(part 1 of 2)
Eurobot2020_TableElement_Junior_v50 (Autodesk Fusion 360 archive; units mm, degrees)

design "TableElement2020" references "Balise Rouge", "Table2020", "Balise Verte"
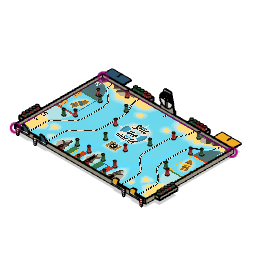
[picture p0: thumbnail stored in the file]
component_insert "Component Insert1"
component_insert "Component Insert21"
component_insert "Component Insert22"
component_insert "Component Insert23"
component_insert "Component Insert24"
component_insert "Component Insert25"
component_insert "Component Insert26"
component_insert "Component Insert27"
component_insert "Component Insert28"
component_insert "Component Insert29"
component_insert "Component Insert30"
component_insert "Component Insert31"
component_insert "Component Insert32"
component_insert "Component Insert33"
component_insert "Component Insert34"
component_insert "Component Insert35"
component_insert "Component Insert36"
component_insert "Component Insert37"
component_insert "Component Insert38"
component_insert "Component Insert39"
component_insert "Component Insert40"
component_insert "Component Insert41"
component_insert "Component Insert42"
component_insert "Component Insert43"
component_insert "Component Insert44"
component_insert "Component Insert45"
component_insert "Component Insert46"
component_insert "Component Insert47"
component_insert "Component Insert48"
component_insert "Component Insert49"
component_insert "Component Insert50"
component_insert "Component Insert51"
component_insert "Component Insert52"
component_insert "Component Insert53"
component_insert "Component Insert54"
component_insert "Component Insert55"
component_insert "Component Insert56"
position "Position1"
joint "Assemble1" OffsetX 0 OffsetY 0 OffsetZ 0 AngleZ 0 OffsetX 0 OffsetY 0 OffsetZ 0 AngleZ 0 alignAngle 0 alignOffsetX 300 alignOffsetY -400 alignOffsetZ 0 OffsetX 0 OffsetY 0 OffsetZ 0 AngleZ 0 OffsetX 0 OffsetY 0 OffsetZ 0 AngleZ 0 OffsetX 0 OffsetY 0 OffsetZ 0 AngleZ 0 OffsetX 0 OffsetY 0 OffsetZ 0 AngleZ 0 OffsetX 0 OffsetY 0 OffsetZ 0 AngleZ 0 OffsetX 0 OffsetY 0 OffsetZ 0 AngleZ 0 OffsetX 0 OffsetY 0 OffsetZ 0 AngleZ 0 OffsetX 0 OffsetY 0 OffsetZ 0 AngleZ 0 OffsetX 0 OffsetY 0 OffsetZ 0 AngleZ 0 OffsetX 0 OffsetY 0 OffsetZ 0 AngleZ 0
joint "Assemble2" OffsetX 0 OffsetY 0 OffsetZ 0 AngleZ 0 OffsetX 0 OffsetY 0 OffsetZ 0 AngleZ 0 alignAngle 0 alignOffsetX 450 alignOffsetY -509 alignOffsetZ 0 OffsetX 0 OffsetY 0 OffsetZ 0 AngleZ 0 OffsetX 0 OffsetY 0 OffsetZ 0 AngleZ 0 OffsetX 0 OffsetY 0 OffsetZ 0 AngleZ 0 OffsetX 0 OffsetY 0 OffsetZ 0 AngleZ 0
joint "Assemble3" OffsetX 0 OffsetY 0 OffsetZ 0 AngleZ 0 OffsetX 0 OffsetY 0 OffsetZ 0 AngleZ 0 alignAngle 0 alignOffsetX 450 alignOffsetY -1080 alignOffsetZ 0 OffsetX 0 OffsetY 0 OffsetZ 0 AngleZ 0 OffsetX 0 OffsetY 0 OffsetZ 0 AngleZ 0
joint "Assemble4" OffsetX 0 OffsetY 0 OffsetZ 0 AngleZ 0 OffsetX 0 OffsetY 0 OffsetZ 0 AngleZ 0 alignAngle 0 alignOffsetX 300 alignOffsetY -1200 alignOffsetZ 0 OffsetX 0 OffsetY 0 OffsetZ 0 AngleZ 0 OffsetX 0 OffsetY 0 OffsetZ 0 AngleZ 0
joint "Assemble5" OffsetX 0 OffsetY 0 OffsetZ 0 AngleZ 0 OffsetX 0 OffsetY 0 OffsetZ 0 AngleZ 0 alignAngle 0 alignOffsetX 670 alignOffsetY -100 alignOffsetZ 0 OffsetX 0 OffsetY 0 OffsetZ 0 AngleZ 0 OffsetX 0 OffsetY 0 OffsetZ 0 AngleZ 0 OffsetX 0 OffsetY 0 OffsetZ 0 AngleZ 0 OffsetX 0 OffsetY 0 OffsetZ 0 AngleZ 0 OffsetX 0 OffsetY 0 OffsetZ 0 AngleZ 0 OffsetX 0 OffsetY 0 OffsetZ 0 AngleZ 0
joint "Assemble6" OffsetX 0 OffsetY 0 OffsetZ 0 AngleZ 0 OffsetX 0 OffsetY 0 OffsetZ 0 AngleZ 0 alignAngle 0 alignOffsetX 950 alignOffsetY -400 alignOffsetZ 0 OffsetX 0 OffsetY 0 OffsetZ 0 AngleZ 0 OffsetX 0 OffsetY 0 OffsetZ 0 AngleZ 0 OffsetX 0 OffsetY 0 OffsetZ 0 AngleZ 0 OffsetX 0 OffsetY 0 OffsetZ 0 AngleZ 0
joint "Assemble7" OffsetX 0 OffsetY 0 OffsetZ 0 AngleZ 0 OffsetX 0 OffsetY 0 OffsetZ 0 AngleZ 0 alignAngle 0 alignOffsetX 1100 alignOffsetY -800 alignOffsetZ 0 OffsetX 0 OffsetY 0 OffsetZ 0 AngleZ 0 OffsetX 0 OffsetY 0 OffsetZ 0 AngleZ 0 OffsetX 0 OffsetY 0 OffsetZ 0 AngleZ 0 OffsetX 0 OffsetY 0 OffsetZ 0 AngleZ 0
joint "Assemble8" OffsetX 0 OffsetY 0 OffsetZ 0 AngleZ 0 OffsetX 0 OffsetY 0 OffsetZ 0 AngleZ 0 alignAngle 0 alignOffsetX 1270 alignOffsetY -1200 alignOffsetZ 0 OffsetX 0 OffsetY 0 OffsetZ 0 AngleZ 0 OffsetX 0 OffsetY 0 OffsetZ 0 AngleZ 0 OffsetX 0 OffsetY 0 OffsetZ 0 AngleZ 0 OffsetX 0 OffsetY 0 OffsetZ 0 AngleZ 0
joint "Assemble9" OffsetX 0 OffsetY 0 OffsetZ 0 AngleZ 0 OffsetX 0 OffsetY 0 OffsetZ 0 AngleZ 0 alignAngle 0 alignOffsetX 1730 alignOffsetY -1200 alignOffsetZ 0 OffsetX 0 OffsetY 0 OffsetZ 0 AngleZ 0 OffsetX 0 OffsetY 0 OffsetZ 0 AngleZ 0
joint "Assemble10" OffsetX 0 OffsetY 0 OffsetZ 0 AngleZ 0 OffsetX 0 OffsetY 0 OffsetZ 0 AngleZ 0 alignAngle 0 alignOffsetX 1900 alignOffsetY -800 alignOffsetZ 0 OffsetX 0 OffsetY 0 OffsetZ 0 AngleZ 0 OffsetX 0 OffsetY 0 OffsetZ 0 AngleZ 0
joint "Assemble11" OffsetX 0 OffsetY 0 OffsetZ 0 AngleZ 0 OffsetX 0 OffsetY 0 OffsetZ 0 AngleZ 0 alignAngle 0 alignOffsetX 2050 alignOffsetY -400 alignOffsetZ 0 OffsetX 0 OffsetY 0 OffsetZ 0 AngleZ 0 OffsetX 0 OffsetY 0 OffsetZ 0 AngleZ 0 OffsetX 0 OffsetY 0 OffsetZ 0 AngleZ 0 OffsetX 0 OffsetY 0 OffsetZ 0 AngleZ 0
joint "Assemble12" OffsetX 0 OffsetY 0 OffsetZ 0 AngleZ 0 OffsetX 0 OffsetY 0 OffsetZ 0 AngleZ 0 alignAngle 0 alignOffsetX 2330 alignOffsetY -100 alignOffsetZ 0 OffsetX 0 OffsetY 0 OffsetZ 0 AngleZ 0 OffsetX 0 OffsetY 0 OffsetZ 0 AngleZ 0
joint "Assemble13" OffsetX 0 OffsetY 0 OffsetZ 0 AngleZ 0 OffsetX 0 OffsetY 0 OffsetZ 0 AngleZ 0 alignAngle 0 alignOffsetX 2700 alignOffsetY -400 alignOffsetZ 0
joint "Assemble14" OffsetX 0 OffsetY 0 OffsetZ 0 AngleZ 0 OffsetX 0 OffsetY 0 OffsetZ 0 AngleZ 0 alignAngle 0 alignOffsetX 2550 alignOffsetY -510 alignOffsetZ 0 OffsetX 0 OffsetY 0 OffsetZ 0 AngleZ 0 OffsetX 0 OffsetY 0 OffsetZ 0 AngleZ 0 OffsetX 0 OffsetY 0 OffsetZ 0 AngleZ 0 OffsetX 0 OffsetY 0 OffsetZ 0 AngleZ 0
joint "Assemble15" OffsetX 0 OffsetY 0 OffsetZ 0 AngleZ 0 OffsetX 0 OffsetY 0 OffsetZ 0 AngleZ 0 alignAngle 0 alignOffsetX 2550 alignOffsetY -1080 alignOffsetZ 0 OffsetX 0 OffsetY 0 OffsetZ 0 AngleZ 0 OffsetX 0 OffsetY 0 OffsetZ 0 AngleZ 0 OffsetX 0 OffsetY 0 OffsetZ 0 AngleZ 0 OffsetX 0 OffsetY 0 OffsetZ 0 AngleZ 0
joint "Assemble16" OffsetX 0 OffsetY 0 OffsetZ 0 AngleZ 0 OffsetX 0 OffsetY 0 OffsetZ 0 AngleZ 0 alignAngle 0 alignOffsetX 2700 alignOffsetY -1200 alignOffsetZ 0
joint "Assemble17" OffsetX 0 OffsetY 0 OffsetZ 0 AngleZ 0 OffsetX 0 OffsetY 0 OffsetZ 0 AngleZ 0 alignAngle 0 alignOffsetX 1335 alignOffsetY -1650 alignOffsetZ 0 OffsetX 0 OffsetY 0 OffsetZ 0 AngleZ 0 OffsetX 0 OffsetY 0 OffsetZ 0 AngleZ 0 OffsetX 0 OffsetY 0 OffsetZ 0 AngleZ 0 OffsetX 0 OffsetY 0 OffsetZ 0 AngleZ 0
joint "Assemble18" OffsetX 0 OffsetY 0 OffsetZ 0 AngleZ 0 OffsetX 0 OffsetY 0 OffsetZ 0 AngleZ 0 alignAngle 0 alignOffsetX 1065 alignOffsetY -1650 alignOffsetZ 0 OffsetX 0 OffsetY 0 OffsetZ 0 AngleZ 0 OffsetX 0 OffsetY 0 OffsetZ 0 AngleZ 0 OffsetX 0 OffsetY 0 OffsetZ 0 AngleZ 0 OffsetX 0 OffsetY 0 OffsetZ 0 AngleZ 0
joint "Assemble19" OffsetX 0 OffsetY 0 OffsetZ 0 AngleZ 0 OffsetX 0 OffsetY 0 OffsetZ 0 AngleZ 0 alignAngle 0 alignOffsetX 1005 alignOffsetY -1955 alignOffsetZ 0 OffsetX 0 OffsetY 0 OffsetZ 0 AngleZ 0 OffsetX 0 OffsetY 0 OffsetZ 0 AngleZ 0 OffsetX 0 OffsetY 0 OffsetZ 0 AngleZ 0 OffsetX 0 OffsetY 0 OffsetZ 0 AngleZ 0 OffsetX 0 OffsetY 0 OffsetZ 0 AngleZ 0 OffsetX 0 OffsetY 0 OffsetZ 0 AngleZ 0 OffsetX 0 OffsetY 0 OffsetZ 0 AngleZ 0 OffsetX 0 OffsetY 0 OffsetZ 0 AngleZ 0
joint "Assemble20" OffsetX 0 OffsetY 0 OffsetZ 0 AngleZ 0 OffsetX 0 OffsetY 0 OffsetZ 0 AngleZ 0 alignAngle 0 alignOffsetX 1395 alignOffsetY -1955 alignOffsetZ 0 OffsetX 0 OffsetY 0 OffsetZ 0 AngleZ 0 OffsetX 0 OffsetY 0 OffsetZ 0 AngleZ 0 OffsetX 0 OffsetY 0 OffsetZ 0 AngleZ 0 OffsetX 0 OffsetY 0 OffsetZ 0 AngleZ 0
joint "Assemble21" OffsetX 0 OffsetY 0 OffsetZ 0 AngleZ 0 OffsetX 0 OffsetY 0 OffsetZ 0 AngleZ 0 alignAngle 0 alignOffsetX 1935 alignOffsetY -1650 alignOffsetZ 0 OffsetX 0 OffsetY 0 OffsetZ 0 AngleZ 0 OffsetX 0 OffsetY 0 OffsetZ 0 AngleZ 0 OffsetX 0 OffsetY 0 OffsetZ 0 AngleZ 0 OffsetX 0 OffsetY 0 OffsetZ 0 AngleZ 0
joint "Assemble22" OffsetX 0 OffsetY 0 OffsetZ 0 AngleZ 0 OffsetX 0 OffsetY 0 OffsetZ 0 AngleZ 0 alignAngle 0 alignOffsetX 1665 alignOffsetY -1650 alignOffsetZ 0 OffsetX 0 OffsetY 0 OffsetZ 0 AngleZ 0 OffsetX 0 OffsetY 0 OffsetZ 0 AngleZ 0 OffsetX 0 OffsetY 0 OffsetZ 0 AngleZ 0 OffsetX 0 OffsetY 0 OffsetZ 0 AngleZ 0
joint "Assemble23" OffsetX 0 OffsetY 0 OffsetZ 0 AngleZ 0 OffsetX 0 OffsetY 0 OffsetZ 0 AngleZ 0 alignAngle 0 alignOffsetX 1605 alignOffsetY -1955 alignOffsetZ 0 OffsetX 0 OffsetY 0 OffsetZ 0 AngleZ 0 OffsetX 0 OffsetY 0 OffsetZ 0 AngleZ 0 OffsetX 0 OffsetY 0 OffsetZ 0 AngleZ 0 OffsetX 0 OffsetY 0 OffsetZ 0 AngleZ 0
joint "Assemble24" OffsetX 0 OffsetY 0 OffsetZ 0 AngleZ 0 OffsetX 0 OffsetY 0 OffsetZ 0 AngleZ 0 alignAngle 0 alignOffsetX 1995 alignOffsetY -1955 alignOffsetZ 0 OffsetX 0 OffsetY 0 OffsetZ 0 AngleZ 0 OffsetX 0 OffsetY 0 OffsetZ 0 AngleZ 0 OffsetX 0 OffsetY 0 OffsetZ 0 AngleZ 0 OffsetX 0 OffsetY 0 OffsetZ 0 AngleZ 0
joint "Assemble25" OffsetX 0 OffsetY 0 OffsetZ 0 AngleZ 0 OffsetX 0 OffsetY 0 OffsetZ 0 AngleZ 0 alignAngle 0 alignOffsetX -67 (= "-22 mm - 45 mm") alignOffsetY -1450 alignOffsetZ 130 OffsetX 0 OffsetY 0 OffsetZ 0 AngleZ 0 OffsetX 0 OffsetY 0 OffsetZ 0 AngleZ 0 OffsetX 0 OffsetY 0 OffsetZ 0 AngleZ 0 OffsetX 0 OffsetY 0 OffsetZ 0 AngleZ 0 OffsetX 0 OffsetY 0 OffsetZ 0 AngleZ 0 OffsetX 0 OffsetY 0 OffsetZ 0 AngleZ 0 OffsetX 0 OffsetY 0 OffsetZ 0 AngleZ 0 OffsetX 0 OffsetY 0 OffsetZ 0 AngleZ 0 OffsetX 0 OffsetY 0 OffsetZ 0 AngleZ 0 OffsetX 0 OffsetY 0 OffsetZ 0 AngleZ 0 OffsetX 0 OffsetY 0 OffsetZ 0 AngleZ 0 OffsetX 0 OffsetY 0 OffsetZ 0 AngleZ 0 OffsetX 0 OffsetY 0 OffsetZ 0 AngleZ 0 OffsetX 0 OffsetY 0 OffsetZ 0 AngleZ 0 OffsetX 0 OffsetY 0 OffsetZ 0 AngleZ 0 OffsetX 0 OffsetY 0 OffsetZ 0 AngleZ 0
joint "Assemble26" OffsetX 0 OffsetY 0 OffsetZ 0 AngleZ 0 OffsetX 0 OffsetY 0 OffsetZ 0 AngleZ 0 alignAngle 0 alignOffsetX -67 (= "-22 mm - 45 mm") alignOffsetY -1525 alignOffsetZ 130 OffsetX 0 OffsetY 0 OffsetZ 0 AngleZ 0 OffsetX 0 OffsetY 0 OffsetZ 0 AngleZ 0 OffsetX 0 OffsetY 0 OffsetZ 0 AngleZ 0 OffsetX 0 OffsetY 0 OffsetZ 0 AngleZ 0 OffsetX 0 OffsetY 0 OffsetZ 0 AngleZ 0 OffsetX 0 OffsetY 0 OffsetZ 0 AngleZ 0 OffsetX 0 OffsetY 0 OffsetZ 0 AngleZ 0 OffsetX 0 OffsetY 0 OffsetZ 0 AngleZ 0 OffsetX 0 OffsetY 0 OffsetZ 0 AngleZ 0 OffsetX 0 OffsetY 0 OffsetZ 0 AngleZ 0 OffsetX 0 OffsetY 0 OffsetZ 0 AngleZ 0 OffsetX 0 OffsetY 0 OffsetZ 0 AngleZ 0
joint "Assemble27" OffsetX 0 OffsetY 0 OffsetZ 0 AngleZ 0 OffsetX 0 OffsetY 0 OffsetZ 0 AngleZ 0 alignAngle 0 alignOffsetX -67 (= "-22 mm - 45 mm") alignOffsetY -1600 alignOffsetZ 130 OffsetX 0 OffsetY 0 OffsetZ 0 AngleZ 0 OffsetX 0 OffsetY 0 OffsetZ 0 AngleZ 0 OffsetX 0 OffsetY 0 OffsetZ 0 AngleZ 0 OffsetX 0 OffsetY 0 OffsetZ 0 AngleZ 0 OffsetX 0 OffsetY 0 OffsetZ 0 AngleZ 0 OffsetX 0 OffsetY 0 OffsetZ 0 AngleZ 0 OffsetX 0 OffsetY 0 OffsetZ 0 AngleZ 0 OffsetX 0 OffsetY 0 OffsetZ 0 AngleZ 0 OffsetX 0 OffsetY 0 OffsetZ 0 AngleZ 0 OffsetX 0 OffsetY 0 OffsetZ 0 AngleZ 0 OffsetX 0 OffsetY 0 OffsetZ 0 AngleZ 0 OffsetX 0 OffsetY 0 OffsetZ 0 AngleZ 0 OffsetX 0 OffsetY 0 OffsetZ 0 AngleZ 0 OffsetX 0 OffsetY 0 OffsetZ 0 AngleZ 0
component_insert "Component Insert66"
joint "Assemble40" OffsetX 0 OffsetY 0 OffsetZ 0 AngleZ 0 OffsetX 0 OffsetY 0 OffsetZ 0 AngleZ 0 alignAngle 0 alignOffsetX -67 alignOffsetY -1675 alignOffsetZ 130 OffsetX 0 OffsetY 0 OffsetZ 0 AngleZ 0 OffsetX 0 OffsetY 0 OffsetZ 0 AngleZ 0 OffsetX 0 OffsetY 0 OffsetZ 0 AngleZ 0 OffsetX 0 OffsetY 0 OffsetZ 0 AngleZ 0 OffsetX 0 OffsetY 0 OffsetZ 0 AngleZ 0 OffsetX 0 OffsetY 0 OffsetZ 0 AngleZ 0 OffsetX 0 OffsetY 0 OffsetZ 0 AngleZ 0 OffsetX 0 OffsetY 0 OffsetZ 0 AngleZ 0
component_insert "Component Insert73"
joint "Assemble46" OffsetX 0 OffsetY 0 OffsetZ 0 AngleZ 0 OffsetX 0 OffsetY 0 OffsetZ 0 AngleZ 0 alignAngle 0 alignOffsetX -67 alignOffsetY -1750 alignOffsetZ 15 OffsetX 0 OffsetY 0 OffsetZ 0 AngleZ 0 OffsetX 0 OffsetY 0 OffsetZ 0 AngleZ 0
joint "Assemble28" OffsetX 0 OffsetY 0 OffsetZ 0 AngleZ 0 OffsetX 0 OffsetY 0 OffsetZ 0 AngleZ 0 alignAngle 0 alignOffsetX 3067 alignOffsetY -1675 alignOffsetZ 130 OffsetX 0 OffsetY 0 OffsetZ 0 AngleZ 0 OffsetX 0 OffsetY 0 OffsetZ 0 AngleZ 0 OffsetX 0 OffsetY 0 OffsetZ 0 AngleZ 0 OffsetX 0 OffsetY 0 OffsetZ 0 AngleZ 0 OffsetX 0 OffsetY 0 OffsetZ 0 AngleZ 0 OffsetX 0 OffsetY 0 OffsetZ 0 AngleZ 0 OffsetX 0 OffsetY 0 OffsetZ 0 AngleZ 0 OffsetX 0 OffsetY 0 OffsetZ 0 AngleZ 0 OffsetX 0 OffsetY 0 OffsetZ 0 AngleZ 0 OffsetX 0 OffsetY 0 OffsetZ 0 AngleZ 0 OffsetX 0 OffsetY 0 OffsetZ 0 AngleZ 0 OffsetX 0 OffsetY 0 OffsetZ 0 AngleZ 0 OffsetX 0 OffsetY 0 OffsetZ 0 AngleZ 0 OffsetX 0 OffsetY 0 OffsetZ 0 AngleZ 0
joint "Assemble29" OffsetX 0 OffsetY 0 OffsetZ 0 AngleZ 0 OffsetX 0 OffsetY 0 OffsetZ 0 AngleZ 0 alignAngle 0 alignOffsetX 3067 alignOffsetY -1750 alignOffsetZ 130 OffsetX 0 OffsetY 0 OffsetZ 0 AngleZ 0 OffsetX 0 OffsetY 0 OffsetZ 0 AngleZ 0 OffsetX 0 OffsetY 0 OffsetZ 0 AngleZ 0 OffsetX 0 OffsetY 0 OffsetZ 0 AngleZ 0 OffsetX 0 OffsetY 0 OffsetZ 0 AngleZ 0 OffsetX 0 OffsetY 0 OffsetZ 0 AngleZ 0 OffsetX 0 OffsetY 0 OffsetZ 0 AngleZ 0 OffsetX 0 OffsetY 0 OffsetZ 0 AngleZ 0 OffsetX 0 OffsetY 0 OffsetZ 0 AngleZ 0 OffsetX 0 OffsetY 0 OffsetZ 0 AngleZ 0 OffsetX 0 OffsetY 0 OffsetZ 0 AngleZ 0 OffsetX 0 OffsetY 0 OffsetZ 0 AngleZ 0 OffsetX 0 OffsetY 0 OffsetZ 0 AngleZ 0 OffsetX 0 OffsetY 0 OffsetZ 0 AngleZ 0
joint "Assemble30" OffsetX 0 OffsetY 0 OffsetZ 0 AngleZ 0 OffsetX 0 OffsetY 0 OffsetZ 0 AngleZ 0 alignAngle 0 alignOffsetX 3067 alignOffsetY -1525 alignOffsetZ 130 OffsetX 0 OffsetY 0 OffsetZ 0 AngleZ 0 OffsetX 0 OffsetY 0 OffsetZ 0 AngleZ 0 OffsetX 0 OffsetY 0 OffsetZ 0 AngleZ 0 OffsetX 0 OffsetY 0 OffsetZ 0 AngleZ 0 OffsetX 0 OffsetY 0 OffsetZ 0 AngleZ 0 OffsetX 0 OffsetY 0 OffsetZ 0 AngleZ 0 OffsetX 0 OffsetY 0 OffsetZ 0 AngleZ 0 OffsetX 0 OffsetY 0 OffsetZ 0 AngleZ 0 OffsetX 0 OffsetY 0 OffsetZ 0 AngleZ 0 OffsetX 0 OffsetY 0 OffsetZ 0 AngleZ 0 OffsetX 0 OffsetY 0 OffsetZ 0 AngleZ 0 OffsetX 0 OffsetY 0 OffsetZ 0 AngleZ 0 OffsetX 0 OffsetY 0 OffsetZ 0 AngleZ 0 OffsetX 0 OffsetY 0 OffsetZ 0 AngleZ 0 OffsetX 0 OffsetY 0 OffsetZ 0 AngleZ 0 OffsetX 0 OffsetY 0 OffsetZ 0 AngleZ 0
component_insert "Component Insert67"
joint "Assemble41" OffsetX 0 OffsetY 0 OffsetZ 0 AngleZ 0 OffsetX 0 OffsetY 0 OffsetZ 0 AngleZ 0 alignAngle 0 alignOffsetX 3067 alignOffsetY -1600 alignOffsetZ 130 OffsetX 0 OffsetY 0 OffsetZ 0 AngleZ 0 OffsetX 0 OffsetY 0 OffsetZ 0 AngleZ 0 OffsetX 0 OffsetY 0 OffsetZ 0 AngleZ 0 OffsetX 0 OffsetY 0 OffsetZ 0 AngleZ 0 OffsetX 0 OffsetY 0 OffsetZ 0 AngleZ 0 OffsetX 0 OffsetY 0 OffsetZ 0 AngleZ 0 OffsetX 0 OffsetY 0 OffsetZ 0 AngleZ 0 OffsetX 0 OffsetY 0 OffsetZ 0 AngleZ 0
component_insert "Component Insert74"
joint "Assemble47" OffsetX 0 OffsetY 0 OffsetZ 0 AngleZ 0 OffsetX 0 OffsetY 0 OffsetZ 0 AngleZ 0 alignAngle 180 alignOffsetX 3067 alignOffsetY -1450 alignOffsetZ 15 OffsetX 0 OffsetY 0 OffsetZ 0 AngleZ 0 OffsetX 0 OffsetY 0 OffsetZ 0 AngleZ 0 OffsetX 0 OffsetY 0 OffsetZ 0 AngleZ 0 OffsetX 0 OffsetY 0 OffsetZ 0 AngleZ 0
ground "Ground1"
ground "Ground2"
joint "Assemble31" OffsetX 0 OffsetY 0 OffsetZ 0 AngleZ 0 OffsetX 0 OffsetY 0 OffsetZ 0 AngleZ 0 alignAngle 0 alignOffsetX 700 alignOffsetY 67 (= "22 mm + 45 mm") alignOffsetZ 130 OffsetX 0 OffsetY 0 OffsetZ 0 AngleZ 0 OffsetX 0 OffsetY 0 OffsetZ 0 AngleZ 0 OffsetX 0 OffsetY 0 OffsetZ 0 AngleZ 0 OffsetX 0 OffsetY 0 OffsetZ 0 AngleZ 0 OffsetX 0 OffsetY 0 OffsetZ 0 AngleZ 0 OffsetX 0 OffsetY 0 OffsetZ 0 AngleZ 0 OffsetX 0 OffsetY 0 OffsetZ 0 AngleZ 0 OffsetX 0 OffsetY 0 OffsetZ 0 AngleZ 0 OffsetX 0 OffsetY 0 OffsetZ 0 AngleZ 0 OffsetX 0 OffsetY 0 OffsetZ 0 AngleZ 0
joint "Assemble32" OffsetX 0 OffsetY 0 OffsetZ 0 AngleZ 0 OffsetX 0 OffsetY 0 OffsetZ 0 AngleZ 0 alignAngle 0 alignOffsetX 850 alignOffsetY 67 alignOffsetZ 130 OffsetX 0 OffsetY 0 OffsetZ 0 AngleZ 0 OffsetX 0 OffsetY 0 OffsetZ 0 AngleZ 0 OffsetX 0 OffsetY 0 OffsetZ 0 AngleZ 0 OffsetX 0 OffsetY 0 OffsetZ 0 AngleZ 0 OffsetX 0 OffsetY 0 OffsetZ 0 AngleZ 0 OffsetX 0 OffsetY 0 OffsetZ 0 AngleZ 0 OffsetX 0 OffsetY 0 OffsetZ 0 AngleZ 0 OffsetX 0 OffsetY 0 OffsetZ 0 AngleZ 0 OffsetX 0 OffsetY 0 OffsetZ 0 AngleZ 0 OffsetX 0 OffsetY 0 OffsetZ 0 AngleZ 0
joint "Assemble33" OffsetX 0 OffsetY 0 OffsetZ 0 AngleZ 0 OffsetX 0 OffsetY 0 OffsetZ 0 AngleZ 0 alignAngle 0 alignOffsetX 1000 alignOffsetY 67 alignOffsetZ 130 OffsetX 0 OffsetY 0 OffsetZ 0 AngleZ 0 OffsetX 0 OffsetY 0 OffsetZ 0 AngleZ 0 OffsetX 0 OffsetY 0 OffsetZ 0 AngleZ 0 OffsetX 0 OffsetY 0 OffsetZ 0 AngleZ 0 OffsetX 0 OffsetY 0 OffsetZ 0 AngleZ 0 OffsetX 0 OffsetY 0 OffsetZ 0 AngleZ 0 OffsetX 0 OffsetY 0 OffsetZ 0 AngleZ 0 OffsetX 0 OffsetY 0 OffsetZ 0 AngleZ 0 OffsetX 0 OffsetY 0 OffsetZ 0 AngleZ 0 OffsetX 0 OffsetY 0 OffsetZ 0 AngleZ 0
component_insert "Component Insert63"
joint "Assemble37" OffsetX 0 OffsetY 0 OffsetZ 0 AngleZ 0 OffsetX 0 OffsetY 0 OffsetZ 0 AngleZ 0 alignAngle 0 alignOffsetX 925 alignOffsetY 67 alignOffsetZ 130 OffsetX 0 OffsetY 0 OffsetZ 0 AngleZ 0 OffsetX 0 OffsetY 0 OffsetZ 0 AngleZ 0 OffsetX 0 OffsetY 0 OffsetZ 0 AngleZ 0 OffsetX 0 OffsetY 0 OffsetZ 0 AngleZ 0 OffsetX 0 OffsetY 0 OffsetZ 0 AngleZ 0 OffsetX 0 OffsetY 0 OffsetZ 0 AngleZ 0
component_insert "Component Insert70"
joint "Assemble44" OffsetX 0 OffsetY 0 OffsetZ 0 AngleZ 0 OffsetX 0 OffsetY 0 OffsetZ 0 AngleZ 0 alignAngle 180 alignOffsetX 775 alignOffsetY 67 alignOffsetZ 15 OffsetX 0 OffsetY 0 OffsetZ 0 AngleZ 0 OffsetX 0 OffsetY 0 OffsetZ 0 AngleZ 0 OffsetX 0 OffsetY 0 OffsetZ 0 AngleZ 0 OffsetX 0 OffsetY 0 OffsetZ 0 AngleZ 0
joint "Assemble34" OffsetX 0 OffsetY 0 OffsetZ 0 AngleZ 0 OffsetX 0 OffsetY 0 OffsetZ 0 AngleZ 0 alignAngle 0 alignOffsetX 2000 alignOffsetY 67 alignOffsetZ 130 OffsetX 0 OffsetY 0 OffsetZ 0 AngleZ 0 OffsetX 0 OffsetY 0 OffsetZ 0 AngleZ 0 OffsetX 0 OffsetY 0 OffsetZ 0 AngleZ 0 OffsetX 0 OffsetY 0 OffsetZ 0 AngleZ 0 OffsetX 0 OffsetY 0 OffsetZ 0 AngleZ 0 OffsetX 0 OffsetY 0 OffsetZ 0 AngleZ 0 OffsetX 0 OffsetY 0 OffsetZ 0 AngleZ 0 OffsetX 0 OffsetY 0 OffsetZ 0 AngleZ 0 OffsetX 0 OffsetY 0 OffsetZ 0 AngleZ 0 OffsetX 0 OffsetY 0 OffsetZ 0 AngleZ 0
joint "Assemble35" OffsetX 0 OffsetY 0 OffsetZ 0 AngleZ 0 OffsetX 0 OffsetY 0 OffsetZ 0 AngleZ 0 alignAngle 0 alignOffsetX 2150 alignOffsetY 67 alignOffsetZ 130 OffsetX 0 OffsetY 0 OffsetZ 0 AngleZ 0 OffsetX 0 OffsetY 0 OffsetZ 0 AngleZ 0 OffsetX 0 OffsetY 0 OffsetZ 0 AngleZ 0 OffsetX 0 OffsetY 0 OffsetZ 0 AngleZ 0 OffsetX 0 OffsetY 0 OffsetZ 0 AngleZ 0 OffsetX 0 OffsetY 0 OffsetZ 0 AngleZ 0 OffsetX 0 OffsetY 0 OffsetZ 0 AngleZ 0 OffsetX 0 OffsetY 0 OffsetZ 0 AngleZ 0 OffsetX 0 OffsetY 0 OffsetZ 0 AngleZ 0 OffsetX 0 OffsetY 0 OffsetZ 0 AngleZ 0 OffsetX 0 OffsetY 0 OffsetZ 0 AngleZ 0 OffsetX 0 OffsetY 0 OffsetZ 0 AngleZ 0 OffsetX 0 OffsetY 0 OffsetZ 0 AngleZ 0 OffsetX 0 OffsetY 0 OffsetZ 0 AngleZ 0 OffsetX 0 OffsetY 0 OffsetZ 0 AngleZ 0 OffsetX 0 OffsetY 0 OffsetZ 0 AngleZ 0 OffsetX 0 OffsetY 0 OffsetZ 0 AngleZ 0 OffsetX 0 OffsetY 0 OffsetZ 0 AngleZ 0 OffsetX 0 OffsetY 0 OffsetZ 0 AngleZ 0 OffsetX 0 OffsetY 0 OffsetZ 0 AngleZ 0
joint "Assemble36" OffsetX 0 OffsetY 0 OffsetZ 0 AngleZ 0 OffsetX 0 OffsetY 0 OffsetZ 0 AngleZ 0 alignAngle 0 alignOffsetX 2075 alignOffsetY 67 alignOffsetZ 130 OffsetX 0 OffsetY 0 OffsetZ 0 AngleZ 0 OffsetX 0 OffsetY 0 OffsetZ 0 AngleZ 0 OffsetX 0 OffsetY 0 OffsetZ 0 AngleZ 0 OffsetX 0 OffsetY 0 OffsetZ 0 AngleZ 0 OffsetX 0 OffsetY 0 OffsetZ 0 AngleZ 0 OffsetX 0 OffsetY 0 OffsetZ 0 AngleZ 0 OffsetX 0 OffsetY 0 OffsetZ 0 AngleZ 0 OffsetX 0 OffsetY 0 OffsetZ 0 AngleZ 0 OffsetX 0 OffsetY 0 OffsetZ 0 AngleZ 0 OffsetX 0 OffsetY 0 OffsetZ 0 AngleZ 0 OffsetX 0 OffsetY 0 OffsetZ 0 AngleZ 0 OffsetX 0 OffsetY 0 OffsetZ 0 AngleZ 0 OffsetX 0 OffsetY 0 OffsetZ 0 AngleZ 0 OffsetX 0 OffsetY 0 OffsetZ 0 AngleZ 0
component_insert "Component Insert64"
joint "Assemble38" OffsetX 0 OffsetY 0 OffsetZ 0 AngleZ 0 OffsetX 0 OffsetY 0 OffsetZ 0 AngleZ 0 alignAngle 0 alignOffsetX 2225 alignOffsetY 67 alignOffsetZ 130 OffsetX 0 OffsetY 0 OffsetZ 0 AngleZ 0 OffsetX 0 OffsetY 0 OffsetZ 0 AngleZ 0 OffsetX 0 OffsetY 0 OffsetZ 0 AngleZ 0 OffsetX 0 OffsetY 0 OffsetZ 0 AngleZ 0 OffsetX 0 OffsetY 0 OffsetZ 0 AngleZ 0 OffsetX 0 OffsetY 0 OffsetZ 0 AngleZ 0 OffsetX 0 OffsetY 0 OffsetZ 0 AngleZ 0 OffsetX 0 OffsetY 0 OffsetZ 0 AngleZ 0
component_insert "Component Insert72"
joint "Assemble45" OffsetX 0 OffsetY 0 OffsetZ 0 AngleZ 0 OffsetX 0 OffsetY 0 OffsetZ 0 AngleZ 0 alignAngle 180 alignOffsetX 2300 alignOffsetY 67 alignOffsetZ 15 OffsetX 0 OffsetY 0 OffsetZ 0 AngleZ 0 OffsetX 0 OffsetY 0 OffsetZ 0 AngleZ 0

design "manchonJaune"
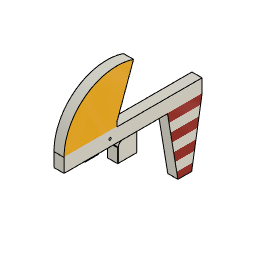
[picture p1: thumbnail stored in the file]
sketch "Sketch1" plane through (0, 0, 0) normal (1, 0, 0) x axis (0, 1, 0)
  line L1 (15, 15) -> (15, 25)
  line L2 (200, 15) -> (15, 15)
  line L3 (-100, -15) -> (125, -15)
  line L4 (-100, 15) -> (-100, -15)
  line L5 (200, 15) -> (200, -15)
  line L6 (177.5, -150) -> (200, -15)
  line L7 (147.5, -150) -> (177.5, -150)
  line L8 (125, -15) -> (147.5, -150)
  line L9 (0, 0) -> (200, 0)
  line L10 (15, 15) -> (-15, 15)
  line L11 (0, 15) -> (0, 0)
  line L12 (51.101, 124.1866) -> (15, 25)
  circle C1 centre (0, 0) radius 2.5
  circle C2 centre (15, 15) radius 115
  point P1 (0, 0)
  point P2 (0, 0)
  point P13 (200, 0)
  point P14 (0, 0)
  point P15 (0, 0)
  point P16 (0, 15)
  point P9 (-100, 15)
  point P5 (15, 15)
  point P17 (15, 15)
  point P18 (51.101, 124.1866)
  point P7 (125, -15)
  point P10 (200, -15)
  point P11 (177.5, -150)
  point P12 (147.5, -150)
  point P8 (-100, -15)
  point P4 (15, 25)
  coincident P1 P2
  perpendicular L1 L2
  horizontal L3
  perpendicular L3 L4
  vertical L5
  equal L4 L5
  parallel L3 L7
  equal L6 L8
  midpoint L5 P13
  coincident P1 P14
  horizontal L9
  coincident P1 P15
  midpoint L10 P16
  vertical L11
  coincident L2 P9
  horizontal L2
  horizontal L10
  equal L4 L10
  coincident P5 P17
  coincident P9 C2
  coincident C2 P18
  dimension "d1" diameter C1 = 5
  dimension "d2" distance P1 L4 = 100
  dimension "d4" distance P2 L5 = 200
  dimension "d8" distance P7 P10 = 75
  dimension "d9" distance P11 P12 = 30
  dimension "d11" distance P8 P9 = 30
  dimension "d12" distance P4 P5 = 10
  dimension "d22" distance L7 L9 = 150
  dimension "d23" angle L2 L12 = 70
  dimension "d36" OffsetX = 0
  dimension "d37" OffsetY = 0
  dimension "d38" OffsetZ = 0
  dimension "d39" AngleZ = 0
  dimension "d48" OffsetX = 0
  dimension "d49" OffsetY = 0
  dimension "d50" OffsetZ = 0
  dimension "d51" AngleZ = 0
extrude "Extrude1" new body sketch "Sketch1" profile of C1 L1 L2 L3 L4 L5 L6 L7 L8 C2 L12 along normal blind 22
sketch "Sketch1" plane through (0, 0, 0) normal (1, 0, 0) x axis (0, 0, -1)
  line L1 (55, 15) -> (15, 15)
  line L2 (55, 55) -> (55, 15)
  line L3 (15, 55) -> (55, 55)
  line L4 (15, 15) -> (15, 55)
  line L5 (15, -100) -> (15, 125)
  line L6 (25, 15) -> (15, 15)
  arc A1 centre (25, 25) radius 10 clockwise from (25, 15) to (15, 25)
  point P8 (25, 15)
  point P9 (15, 25)
  point P1 (0, 0)
  horizontal L1
  vertical L2
  horizontal L3
  vertical L4
  coincident L1 P8
  perpendicular L5 L6
  tangent L6 A1
  coincident L4 P9
  tangent L4 A1
  dimension "d24" distance P1 L1 = 15
  dimension "d25" distance P1 L4 = 15
  dimension "d26" distance P1 L5 = 15
  dimension "d27" distance L4 P8 = 10
  dimension "d28" distance L1 L3 = 40
  dimension "d29" distance L2 L4 = 40
  dimension "d32" OffsetX = 0
  dimension "d33" OffsetY = 0
  dimension "d34" OffsetZ = 0
  dimension "d35" AngleZ = 0
  dimension "d44" OffsetX = 0
  dimension "d45" OffsetY = 0
  dimension "d46" OffsetZ = 0
  dimension "d47" AngleZ = 0
extrude "Extrude1" new body sketch "Sketch1" profile of L1 L2 L3 L4 L5 A1 along normal blind 22
joint "Assemble1" alignAngle 0 alignOffsetX -25 alignOffsetY -28 alignOffsetZ 0
decal "Decal1"
decal "Decal2"
sketch "Sketch1" plane through (0, 18, 0) normal (0, -1, 0) x axis (1, 0, 0)
  line L1 (0, -55) -> (0, -25)
  line L2 (22, -55) -> (0, -55)
  line L3 (22, -25) -> (22, -55)
  line L4 (0, -25) -> (22, -25)
extrude "Extrude1" new body sketch "Sketch1" along normal blind 1.5
position "Position1" RotateAboutZ -90
sketch "Sketch2" plane through (0, 0, -15) normal (0, 0, -1) x axis (1, 0, 0)
  line L1 (0, -125) -> (0, 100)
  line L2 (22, -125) -> (0, -125)
  line L3 (22, 100) -> (22, -125)
  line L4 (0, 100) -> (22, 100)
  line L5 (0, 55) -> (0, 25)
  line L6 (22, 55) -> (0, 55)
  line L7 (22, 25) -> (22, 55)
  line L8 (0, 25) -> (22, 25)
extrude "Extrude2" new body sketch "Sketch2" profile of L1 L3 L5 L6 L7 L8 along normal blind 1.5
position "Position2" RotateAboutZ 0
joint "Assemble2" alignAngle 0 alignOffsetX 0 alignOffsetY 0 alignOffsetZ 0
joint "Assemble3" alignAngle 0 alignOffsetX 0 alignOffsetY 45 alignOffsetZ 0
copy_paste_bodies "CutPasteBodies"
component_from_bodies "Body->Comp"
joint "Assemble4" alignAngle 0 alignOffsetX 0 alignOffsetY 45 alignOffsetZ 0
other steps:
base_feature "Base Feature1"
base_feature "Base Feature1"
create_component "CreateComponent1"
create_component "CreateComponent2"
joint_origin "JointOrigin3" OffsetX 0 OffsetY 0 OffsetZ 0 AngleZ 0
joint_origin "JointOrigin3" OffsetX 0 OffsetY 0 OffsetZ 0 AngleZ 0
joint_origin "JointOrigin1" OffsetX 0 OffsetY 0 OffsetZ 0 AngleZ 0
joint_origin "JointOrigin4" OffsetX 0 OffsetY 0 OffsetZ 0 AngleZ 0
joint_origin "JointOrigin2" OffsetX 0 OffsetY 0 OffsetZ 0 AngleZ 0
joint_origin "JointOrigin4" OffsetX 0 OffsetY 0 OffsetZ 0 AngleZ 0
remove_body "RemoveBody1"
create_component "CreateComponent3"
remove_body "RemoveBody1"
joint_origin "JointOrigin1" OffsetX 0 OffsetY 0 OffsetZ 0 AngleZ 0
joint_origin "JointOrigin5" OffsetX 0 OffsetY 0 OffsetZ 0 AngleZ 0

design "PaintExperience"
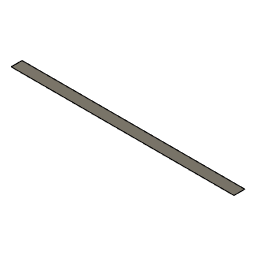
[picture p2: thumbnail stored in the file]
sketch "Sketch1" plane through (0, 0, 0) normal (0, 1, 0) x axis (1, 0, 0)
  line L1 (450, 0) -> (0, 0)
  line L2 (0, 0) -> (450, -22)
  line L3 (0, 0) -> (0, -22)
  line L4 (0, 0) -> (0, 0)
  point P1 (0, 0)
  point P2 (0, 0)
  point P3 (450, 0)
  point P5 (0, -22)
  horizontal L1
  vertical L2
  horizontal L3
  vertical L4
  coincident P1 P2
  dimension "d1" distance P2 P3 = 450
  dimension "d2" distance P2 P5 = 22
extrude "Extrude1" new body sketch "Sketch1" along normal blind 0.1

design "EdgeBeacons_SmallBorder"
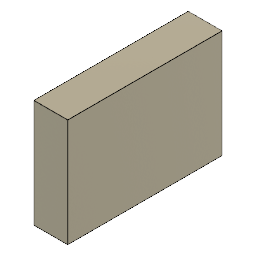
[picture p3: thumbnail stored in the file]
sketch "Sketch1" plane through (0, 0, 0) normal (1, 0, 0) x axis (0, 0, -1)
  line L1 (100, 70) -> (0, 70)
  line L2 (100, 0) -> (100, 70)
  line L3 (0, 0) -> (100, 0)
  line L4 (0, 70) -> (0, 0)
  point P1 (0, 0)
  point P5 (0, 0)
  point P2 (0, 70)
  point P3 (100, 70)
  horizontal L1
  vertical L2
  horizontal L3
  vertical L4
  coincident P1 P5
  dimension "d1" distance P2 P5 = 70 (= "48 mm + 22 mm")
  dimension "d2" distance P2 P3 = 100 (= "122 mm - 22 mm")
extrude "Extrude1" new body sketch "Sketch1" along normal blind 22

design "BaseTable" references "BorderSmall", "MiddleBeaconVertSupport2", "Edge Beacon Right", "Ground", "Edge Beacon Left", "MiddleBeaconVertSupport1", "BorderLong", "MiddleBeaconTop"
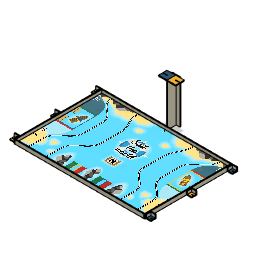
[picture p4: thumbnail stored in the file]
component_insert "Component Insert1"
ground "Ground4"
component_insert "Component Insert2"
component_insert "Component Insert3"
component_insert "Component Insert4"
component_insert "Component Insert5"
joint "Assemble1" OffsetX 0 OffsetY 0 OffsetZ 0 AngleZ 0 OffsetX 0 OffsetY 0 OffsetZ 0 AngleZ 0 alignAngle 0 alignOffsetX 0 alignOffsetY 0 alignOffsetZ 0
joint "Assemble2" OffsetX 0 OffsetY 0 OffsetZ 0 AngleZ 0 OffsetX 0 OffsetY 0 OffsetZ 0 AngleZ 0 alignAngle 0 alignOffsetX 0 alignOffsetY 0 alignOffsetZ 0
joint "Assemble3" OffsetX 0 OffsetY 0 OffsetZ 0 AngleZ 0 OffsetX 0 OffsetY 0 OffsetZ 0 AngleZ 0 alignAngle 0 alignOffsetX 0 alignOffsetY 0 alignOffsetZ 0
joint "Assemble4" OffsetX 0 OffsetY 0 OffsetZ 0 AngleZ 0 OffsetX 0 OffsetY 0 OffsetZ 0 AngleZ 0 alignAngle 0 alignOffsetX 0 alignOffsetY 0 alignOffsetZ 0
component_insert "Component Insert6"
component_insert "Component Insert7"
component_insert "Component Insert8"
component_insert "Component Insert9"
component_insert "Component Insert10"
component_insert "Component Insert11"
joint "Assemble6" OffsetX 0 OffsetY 0 OffsetZ 0 AngleZ 0 OffsetX 0 OffsetY 0 OffsetZ 0 AngleZ 0 alignAngle 180 alignOffsetX 0 alignOffsetY 0 alignOffsetZ 0
joint "Assemble7" OffsetX 0 OffsetY 0 OffsetZ 0 AngleZ 0 OffsetX 0 OffsetY 0 OffsetZ 0 AngleZ 0 alignAngle 180 alignOffsetX 0 alignOffsetY -22 alignOffsetZ 0 OffsetX 0 OffsetY 0 OffsetZ 0 AngleZ 0 OffsetX 0 OffsetY 0 OffsetZ 0 AngleZ 0
joint "Assemble8" OffsetX 0 OffsetY 0 OffsetZ 0 AngleZ 0 OffsetX 0 OffsetY 0 OffsetZ 0 AngleZ 0 alignAngle -90 alignOffsetX 0 alignOffsetY 0 alignOffsetZ 0
joint "Assemble9" OffsetX 0 OffsetY 0 OffsetZ 0 AngleZ 0 OffsetX 0 OffsetY 0 OffsetZ 0 AngleZ 0 alignAngle 0 alignOffsetX -22 alignOffsetY 0 alignOffsetZ 0 OffsetX 0 OffsetY 0 OffsetZ 0 AngleZ 0 OffsetX 0 OffsetY 0 OffsetZ 0 AngleZ 0
joint "Assemble10" OffsetX 0 OffsetY 0 OffsetZ 0 AngleZ 0 OffsetX 0 OffsetY 0 OffsetZ 0 AngleZ 0 alignAngle 180 alignOffsetX 11 alignOffsetY 0 alignOffsetZ 0 OffsetX 0 OffsetY 0 OffsetZ 0 AngleZ 0 OffsetX 0 OffsetY 0 OffsetZ 0 AngleZ 0
joint "Assemble11" OffsetX 0 OffsetY 0 OffsetZ 0 AngleZ 0 OffsetX 0 OffsetY 0 OffsetZ 0 AngleZ 0 alignAngle 180 alignOffsetX -11 alignOffsetY 0 alignOffsetZ 0 OffsetX 0 OffsetY 0 OffsetZ 0 AngleZ 0 OffsetX 0 OffsetY 0 OffsetZ 0 AngleZ 0
component_insert "Component Insert12"
component_insert "Component Insert13"
component_insert "Component Insert14"
joint "Assemble12" OffsetX 0 OffsetY 0 OffsetZ 0 AngleZ 0 OffsetX 0 OffsetY 0 OffsetZ 0 AngleZ 0 alignAngle 0 alignOffsetX 0 alignOffsetY 0 alignOffsetZ 0
joint "Assemble13" OffsetX 0 OffsetY 0 OffsetZ 0 AngleZ 0 OffsetX 0 OffsetY 0 OffsetZ 0 AngleZ 0 alignAngle 0 alignOffsetX 0 alignOffsetY 0 alignOffsetZ 0
joint "Assemble14" OffsetX 0 OffsetY 0 OffsetZ 0 AngleZ 0 OffsetX 0 OffsetY 0 OffsetZ 0 AngleZ 0 alignAngle 180 alignOffsetX 0 alignOffsetY -22 alignOffsetZ 0

design "EdgeBeacons_Base"
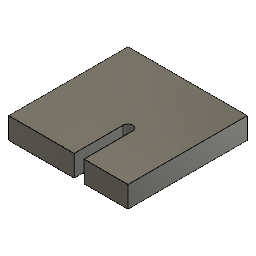
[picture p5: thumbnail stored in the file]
sketch "Sketch1" plane through (0, 0, 0) normal (0, 1, 0) x axis (1, 0, 0)
  line L1 (61, 61) -> (-61, 61)
  line L2 (61, -61) -> (61, 61)
  line L3 (-61, 61) -> (-61, -61)
  line L4 (61, -61) -> (-61, 61)
  line L5 (16, -11) -> (16, -61)
  line L6 (6, -61) -> (6, -11)
  line L7 (11, -11) -> (11, -61)
  line L8 (16, -61) -> (61, -61)
  line L9 (-61, -61) -> (6, -61)
  arc A1 centre (11, -11) radius 5 clockwise from (6, -11) to (16, -11)
  point P2 (-61, 61)
  point P3 (61, 61)
  point P10 (11, -61)
  point P11 (11, -11)
  dimension "d1" distance P2 P3 = 122
  dimension "d4" distance P10 P11 = 50
  dimension "d5" diameter A1 = 10
  dimension "d6" distance L2 L7 = 50
extrude "Extrude1" new body sketch "Sketch1" profile of L1 L2 L9 L3 along normal blind 22

design "EdgeBeacons_LargeBorder"
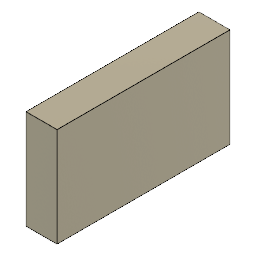
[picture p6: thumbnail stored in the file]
sketch "Sketch1" plane through (0, 0, 0) normal (1, 0, 0) x axis (0, 0, -1)
  line L1 (122, 70) -> (0, 70)
  line L2 (122, 0) -> (122, 70)
  line L3 (0, 0) -> (122, 0)
  line L4 (0, 70) -> (0, 0)
  point P1 (0, 0)
  point P5 (0, 0)
  point P2 (0, 70)
  point P3 (122, 70)
  horizontal L1
  vertical L2
  horizontal L3
  vertical L4
  coincident P1 P5
  dimension "d1" distance P2 P5 = 70 (= "48 mm + 22 mm")
  dimension "d2" distance P2 P3 = 122
extrude "Extrude1" new body sketch "Sketch1" along normal blind 22

design "TaquetCentre"
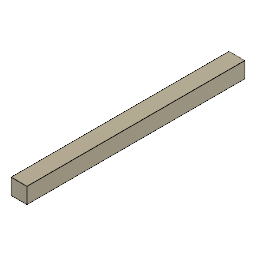
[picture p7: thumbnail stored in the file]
sketch "Sketch1" plane through (0, 0, 0) normal (0, 1, 0) x axis (1, 0, 0)
  line L1 (11, 0) -> (-11, 0)
  line L2 (11, 300) -> (11, 0)
  line L3 (11, 0) -> (-11, 300)
  line L4 (-11, 0) -> (-11, 300)
  point P1 (0, 0)
  horizontal L1
  vertical L2
  horizontal L3
  vertical L4
  dimension "d1" = 300
  dimension "d2" distance P1 L2 = 11
  dimension "d3" distance L2 L4 = 22
extrude "Extrude1" new body sketch "Sketch1" along normal blind 22

design "Table2020" references "TaquetCentre", "PaintExperience", "manchonJaune", "manchonBleu", "taquet", "ROUE_MINI_V3_ASSEMBLAGE", "BaseTable", "Rocher", "ZoneRocheuse"
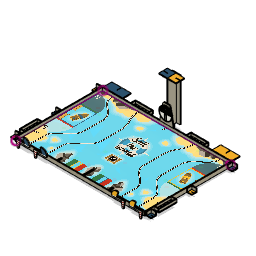
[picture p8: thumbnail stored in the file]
component_insert "Component Insert1" OffsetX 0 OffsetY 0 OffsetZ 0 AngleZ 0 OffsetX 0 OffsetY 0 OffsetZ 0 AngleZ 0 OffsetX 0 OffsetY 0 OffsetZ 0 AngleZ 0 OffsetX 0 OffsetY 0 OffsetZ 0 AngleZ 0 OffsetX 0 OffsetY 0 OffsetZ 0 AngleZ 0 OffsetX 0 OffsetY 0 OffsetZ 0 AngleZ 0 OffsetX 0 OffsetY 0 OffsetZ 0 AngleZ 0 OffsetX 0 OffsetY 0 OffsetZ 0 AngleZ 0
ground "Ground1"
sketch "Sketch1" plane through (0, 22, 0) normal (0, 1, 0) x axis (-1, 0, 0)
  line L1 (-3000, 2000) -> (0, 2000)
  line L2 (-3000, 0) -> (-3000, 2000)
  line L3 (0, 0) -> (-3000, 0)
  line L4 (0, 2000) -> (0, 0)
component_insert "Component Insert7"
component_insert "Component Insert23"
position "Position9"
component_insert "Component Insert24"
position "Position10"
component_insert "Component Insert25"
component_insert "Component Insert26"
position "Position11"
component_insert "Component Insert27"
position "Position12"
joint "Assemble17" OffsetX 0 OffsetY 0 OffsetZ 0 AngleZ 0 OffsetX 0 OffsetY 0 OffsetZ 0 AngleZ 0 alignAngle 0 alignOffsetX 0 alignOffsetY 0 alignOffsetZ 0
joint "Assemble18" OffsetX 0 OffsetY 0 OffsetZ 0 AngleZ 0 OffsetX 0 OffsetY 0 OffsetZ 0 AngleZ 0 alignAngle 0 alignOffsetX 0 alignOffsetY 0 alignOffsetZ 0
position "Position13"
component_insert "Component Insert29"
joint "Assemble24" OffsetX 0 OffsetY 0 OffsetZ 0 AngleZ 0 OffsetX 0 OffsetY 0 OffsetZ 0 AngleZ 0 alignAngle 90 alignOffsetX -2770 alignOffsetY -25 alignOffsetZ 0
component_insert "Component Insert30"
joint "Assemble25" OffsetX 0 OffsetY 0 OffsetZ 0 AngleZ 0 OffsetX 0 OffsetY 0 OffsetZ 0 AngleZ 0 alignAngle 0 alignOffsetX -25 alignOffsetY -2360 alignOffsetZ 0 OffsetX 0 OffsetY 0 OffsetZ 0 AngleZ 0 OffsetX 0 OffsetY 0 OffsetZ 0 AngleZ 0
component_insert "Component Insert33"
joint "Assemble28" OffsetX 0 OffsetY 0 OffsetZ 0 AngleZ 0 alignAngle 0 alignOffsetX 0 alignOffsetY 0 alignOffsetZ 900 OffsetX 0 OffsetY 0 OffsetZ 0 AngleZ 0 OffsetX 0 OffsetY 0 OffsetZ 0 AngleZ 0
component_insert "Component Insert34"
joint "Assemble29" OffsetX 0 OffsetY 0 OffsetZ 0 AngleZ 0 OffsetX 0 OffsetY 0 OffsetZ 0 AngleZ 0 alignAngle 0 alignOffsetX 0 alignOffsetY 0 alignOffsetZ 2100 OffsetX 0 OffsetY 0 OffsetZ 0 AngleZ 0 OffsetX 0 OffsetY 0 OffsetZ 0 AngleZ 0
joint "Assemble30" OffsetX 0 OffsetY 0 OffsetZ 0 AngleZ 0 OffsetX 0 OffsetY 0 OffsetZ 0 AngleZ 0 alignAngle 0 alignOffsetX -22 alignOffsetY 15 alignOffsetZ -850 OffsetX 0 OffsetY 0 OffsetZ 0 AngleZ 0 OffsetX 0 OffsetY 0 OffsetZ 0 AngleZ 0 OffsetX 0 OffsetY 0 OffsetZ 0 AngleZ 0 OffsetX 0 OffsetY 0 OffsetZ 0 AngleZ 0 OffsetX 0 OffsetY 0 OffsetZ 0 AngleZ 0 OffsetX 0 OffsetY 0 OffsetZ 0 AngleZ 0
joint "Assemble31" OffsetX 0 OffsetY 0 OffsetZ 0 AngleZ 0 OffsetX 0 OffsetY 0 OffsetZ 0 AngleZ 0 alignAngle 0 alignOffsetX -22 alignOffsetY 15 alignOffsetZ -2150 (= "-3000 mm + 850 mm") OffsetX 0 OffsetY 0 OffsetZ 0 AngleZ 0 OffsetX 0 OffsetY 0 OffsetZ 0 AngleZ 0 OffsetX 0 OffsetY 0 OffsetZ 0 AngleZ 0 OffsetX 0 OffsetY 0 OffsetZ 0 AngleZ 0 OffsetX 0 OffsetY 0 OffsetZ 0 AngleZ 0 OffsetX 0 OffsetY 0 OffsetZ 0 AngleZ 0 OffsetX 0 OffsetY 0 OffsetZ 0 AngleZ 0 OffsetX 0 OffsetY 0 OffsetZ 0 AngleZ 0
joint "Assemble32" OffsetX 0 OffsetY 0 OffsetZ 0 AngleZ 0 alignAngle 0 alignOffsetX -22 alignOffsetY 15 alignOffsetZ 1600 OffsetX 0 OffsetY 0 OffsetZ 0 AngleZ 0 OffsetX 0 OffsetY 0 OffsetZ 0 AngleZ 0 OffsetX 0 OffsetY 0 OffsetZ 0 AngleZ 0
joint "Assemble33" OffsetX 0 OffsetY 0 OffsetZ 0 AngleZ 0 alignAngle 180 alignOffsetX 22 alignOffsetY -15 alignOffsetZ -1600 OffsetX 0 OffsetY 0 OffsetZ 0 AngleZ 0 OffsetX 0 OffsetY 0 OffsetZ 0 AngleZ 0 OffsetX 0 OffsetY 0 OffsetZ 0 AngleZ 0
component_insert "Component Insert38"
joint "Assemble38" OffsetX 0 OffsetY 0 OffsetZ 0 AngleZ 0 OffsetX 0 OffsetY 0 OffsetZ 0 AngleZ 0 alignAngle 0 alignOffsetX 0 alignOffsetY 0 alignOffsetZ 0 OffsetX 0 OffsetY 0 OffsetZ 0 AngleZ 0 OffsetX 0 OffsetY 0 OffsetZ 0 AngleZ 0
component_insert "Component Insert37"
position "Position14"
joint "Assemble35" OffsetX 0 OffsetY 0 OffsetZ 0 AngleZ 0 OffsetX 0 OffsetY 0 OffsetZ 0 AngleZ 0 alignAngle 0 alignOffsetX 0 alignOffsetY 70 alignOffsetZ 0 OffsetX 0 OffsetY 0 OffsetZ 0 AngleZ 0 OffsetX 0 OffsetY 0 OffsetZ 0 AngleZ 0 OffsetX 0 OffsetY 0 OffsetZ 0 AngleZ 0 OffsetX 0 OffsetY 0 OffsetZ 0 AngleZ 0
sketch "Sketch3" plane through (0, 92, 0) normal (0, 1, 0) x axis (-1, 0, 0)
  line L1 (-3000, 2022) -> (0, 2022)
  line L2 (-3000, 2000) -> (-3000, 2022)
  line L3 (0, 2000) -> (-3000, 2000)
  line L4 (0, 2022) -> (0, 2000)
  line L5 (-1050, 2022) -> (-1050, 2000)
  line L6 (-1150, 2022) -> (-1150, 2000)
  line L7 (-1250, 2022) -> (-1250, 2000)
  line L8 (-1350, 2022) -> (-1350, 2000)
  line L9 (-1650, 2022) -> (-1650, 2000)
  line L10 (-1750, 2022) -> (-1750, 2000)
  line L11 (-1850, 2022) -> (-1850, 2000)
  line L12 (-1950, 2022) -> (-1950, 2000)
  line L13 (-2365, 2022) -> (-2365, 2000)
  line L14 (-2770, 2022) -> (-2770, 2000)
  line L15 (-230, 2022) -> (-230, 2000)
  line L16 (-635, 2022) -> (-635, 2000)
  line L17 (-400, 2022) -> (-400, 2000)
  point P6 (-1050, 2000)
  point P7 (-1050, 2022)
  point P8 (-1150, 2000)
  point P9 (-1150, 2022)
  point P10 (-1250, 2000)
  point P11 (-1250, 2022)
  point P12 (-1350, 2000)
  point P13 (-1350, 2022)
  point P14 (-1650, 2000)
  point P15 (-1650, 2022)
  point P16 (-1750, 2000)
  point P17 (-1750, 2022)
  point P18 (-1850, 2000)
  point P19 (-1850, 2022)
  point P20 (-1950, 2000)
  point P21 (-1950, 2022)
  point P22 (-2365, 2000)
  point P23 (-2365, 2022)
  point P24 (-2770, 2000)
  point P25 (-2770, 2022)
  point P26 (-230, 2000)
  point P27 (-230, 2022)
  point P28 (-635, 2000)
  point P29 (-635, 2022)
  point P30 (-400, 2000)
  point P31 (-400, 2022)
  coincident L3 P6
  coincident L1 P7
  perpendicular L1 L5
  coincident L3 P8
  coincident L1 P9
  perpendicular L1 L6
  coincident L3 P10
  coincident L1 P11
  perpendicular L1 L7
  coincident L3 P12
  coincident L1 P13
  perpendicular L1 L8
  coincident L3 P14
  coincident L1 P15
  perpendicular L1 L9
  coincident L3 P16
  coincident L1 P17
  perpendicular L1 L10
  coincident L3 P18
  coincident L1 P19
  perpendicular L1 L11
  coincident L3 P20
  coincident L1 P21
  perpendicular L1 L12
  coincident L3 P22
  coincident L1 P23
  perpendicular L1 L13
  coincident L3 P24
  coincident L1 P25
  perpendicular L1 L14
  coincident L3 P26
  coincident L1 P27
  perpendicular L1 L15
  coincident L3 P28
  coincident L1 P29
  perpendicular L1 L16
  coincident L3 P30
  coincident L1 P31
  perpendicular L1 L17
  dimension "d685" distance L4 L5 = 1050
  dimension "d686" distance L4 L6 = 1150
  dimension "d687" distance L4 L7 = 1250
  dimension "d688" distance L4 L8 = 1350
  dimension "d689" distance L2 L12 = 1050
  dimension "d690" distance L2 L11 = 1150
  dimension "d691" distance L2 L10 = 1250
  dimension "d692" distance L2 L9 = 1350
  dimension "d693" distance L2 L14 = 230
  dimension "d694" distance L2 L13 = 635
  dimension "d695" distance L4 L15 = 230
  dimension "d696" distance L4 L16 = 635
  dimension "d705" distance L4 L17 = 400
sketch "Sketch4" plane through (0, 92, 0) normal (0, 1, 0) x axis (-1, 0, 0)
  line L1 (22, 2022) -> (22, -22)
  line L2 (0, 2022) -> (22, 2022)
  line L3 (0, -22) -> (0, 2022)
  line L4 (22, -22) -> (0, -22)
  line L5 (22, 1700) -> (0, 1700)
  line L6 (22, 1600) -> (0, 1600)
  line L7 (22, 1500) -> (0, 1500)
  line L8 (22, 1100) -> (0, 1100)
  line L9 (22, 1070) -> (0, 1070)
  line L10 (22, 530) -> (0, 530)
  line L11 (22, 500) -> (0, 500)
  line L12 (22, 100) -> (0, 100)
  line L13 (0, 0) -> (-3000, 0)
  point P6 (0, 1700)
  point P7 (22, 1700)
  point P8 (0, 1600)
  point P9 (22, 1600)
  point P10 (0, 1500)
  point P11 (22, 1500)
  point P12 (0, 1100)
  point P13 (22, 1100)
  point P14 (0, 1070)
  point P15 (22, 1070)
  point P16 (0, 530)
  point P17 (22, 530)
  point P18 (0, 500)
  point P19 (22, 500)
  point P20 (0, 100)
  point P21 (22, 100)
  coincident L3 P6
  coincident L1 P7
  perpendicular L1 L5
  coincident L3 P8
  coincident L1 P9
  perpendicular L1 L6
  coincident L3 P10
  coincident L1 P11
  perpendicular L1 L7
  coincident L3 P12
  coincident L1 P13
  perpendicular L1 L8
  coincident L3 P14
  coincident L1 P15
  perpendicular L1 L9
  coincident L3 P16
  coincident L1 P17
  perpendicular L1 L10
  coincident L3 P18
  coincident L1 P19
  perpendicular L1 L11
  coincident L3 P20
  coincident L1 P21
  perpendicular L1 L12
  dimension "d697" distance L7 L13 = 1500
  dimension "d698" distance L8 L13 = 1100
  dimension "d699" distance L9 L13 = 1070
  dimension "d700" distance L10 L13 = 530
  dimension "d701" distance L11 L13 = 500
  dimension "d702" distance L12 L13 = 100
  dimension "d703" distance L6 L13 = 1600
  dimension "d704" distance L5 L13 = 1700
sketch "Sketch1" plane through (0, 92, 0) normal (0, 1, 0) x axis (-1, 0, 0)
  line L1 (134, 1390.5) -> (112, 1390.5)
  line L2 (134, 1809.5) -> (134, 1390.5)
  line L3 (112, 1809.5) -> (134, 1809.5)
  line L4 (112, 1390.5) -> (112, 1809.5)
  line L5 (0, 1809.5) -> (134, 1809.5)
  line L6 (0, 1390.5) -> (0, 1809.5)
  line L7 (134, 1390.5) -> (0, 1390.5)
  line L8 (134, 1809.5) -> (134, 1390.5)
  line L9 (22, 1412.5) -> (22, 1787.5)
  line L10 (112, 1412.5) -> (22, 1412.5)
  line L11 (112, 1787.5) -> (112, 1412.5)
  line L12 (22, 1787.5) -> (112, 1787.5)
  circle C1 centre (67, 1450) radius 28
  circle C2 centre (67, 1525) radius 28
  circle C3 centre (67, 1600) radius 28
  circle C4 centre (67, 1675) radius 28
  circle C5 centre (67, 1750) radius 28
  point P4 (134, 1809.5)
  point P6 (134, 1809.5)
  horizontal L5
  vertical L6
  horizontal L7
  vertical L8
  coincident P4 P6
  dimension "d726" distance L5 L7 = 419
extrude "Extrude1" new body sketch "Sketch1" profile of L1 L2 L3 L4 L5 L6 L7 L8 L9 L10 L11 L12 along normal blind 0.3
sketch "Sketch1" plane through (0, 92, 0) normal (0, 1, 0) x axis (-1, 0, 0)
  line L1 (-3134, 1809.5) -> (-3112, 1809.5)
  line L2 (-3134, 1390.5) -> (-3134, 1809.5)
  line L3 (-3112, 1390.5) -> (-3134, 1390.5)
  line L4 (-3112, 1809.5) -> (-3112, 1390.5)
  line L5 (-3000, 1390.5) -> (-3134, 1390.5)
  line L6 (-3000, 1809.5) -> (-3000, 1390.5)
  line L7 (-3134, 1809.5) -> (-3000, 1809.5)
  line L8 (-3134, 1390.5) -> (-3134, 1809.5)
  line L9 (-3022, 1787.5) -> (-3022, 1412.5)
  line L10 (-3112, 1787.5) -> (-3022, 1787.5)
  line L11 (-3112, 1412.5) -> (-3112, 1787.5)
  line L12 (-3022, 1412.5) -> (-3112, 1412.5)
  circle C1 centre (-3067, 1750) radius 28
  circle C2 centre (-3067, 1675) radius 28
  circle C3 centre (-3067, 1600) radius 28
  circle C4 centre (-3067, 1525) radius 28
  circle C5 centre (-3067, 1450) radius 28
  point P4 (-3134, 1390.5)
  point P6 (-3134, 1390.5)
  horizontal L5
  vertical L6
  horizontal L7
  vertical L8
  coincident P4 P6
  dimension "d729" distance L5 L7 = 419
extrude "Extrude1" new body sketch "Sketch1" profile of L1 L2 L3 L4 L5 L6 L7 L8 L9 L10 L11 L12 along normal blind 0.3
sketch "Sketch1" plane through (0, 22, 0) normal (0, 1, 0) x axis (-1, 0, 0)
  line L1 (-3000, 2000) -> (0, 2000)
  line L2 (-3000, 0) -> (-3000, 2000)
  line L3 (0, 0) -> (-3000, 0)
  line L4 (0, 2000) -> (0, 0)
  line L5 (-1550, 1200) -> (-1450, 1200)
  line L6 (-1550, 1300) -> (-1550, 1200)
  line L7 (-1450, 1300) -> (-1550, 1300)
  line L8 (-1450, 1200) -> (-1450, 1300)
  line L9 (0, 2022) -> (0, -22)
  line L10 (0, 0) -> (-3000, 0)
  point P6 (-1450, 1200)
  point P7 (-1550, 1200)
  point P9 (-1450, 1300)
  horizontal L5
  vertical L6
  horizontal L7
  vertical L8
  dimension "d732" distance L8 L9 = 1450
  dimension "d733" distance L5 L10 = 1200
  dimension "d734" distance P6 P7 = 100
  dimension "d735" distance P6 P9 = 100
component_insert "Component Insert39"
joint "Assemble39" OffsetX 0 OffsetY 0 OffsetZ 0 AngleZ 0 OffsetX 0 OffsetY 0 OffsetZ 0 AngleZ 0 alignAngle 0 alignOffsetX -25 alignOffsetY -230 alignOffsetZ 0
component_insert "Component Insert40"
joint "Assemble40" OffsetX 0 OffsetY 0 OffsetZ 0 AngleZ 0 OffsetX 0 OffsetY 0 OffsetZ 0 AngleZ 0 alignAngle 0 alignOffsetX -25 alignOffsetY -635 alignOffsetZ 0
component_insert "Component Insert41"
joint "Assemble41" OffsetX 0 OffsetY 0 OffsetZ 0 AngleZ 0 OffsetX 0 OffsetY 0 OffsetZ 0 AngleZ 0 alignAngle 0 alignOffsetX 0 alignOffsetY 0 alignOffsetZ 0 OffsetX 0 OffsetY 0 OffsetZ 0 AngleZ 0 OffsetX 0 OffsetY 0 OffsetZ 0 AngleZ 0
component_insert "Component Insert42"
joint "Assemble43" OffsetX 0 OffsetY 0 OffsetZ 0 AngleZ 0 OffsetX 0 OffsetY 0 OffsetZ 0 AngleZ 0 alignAngle -90 alignOffsetX 0 alignOffsetY 0 alignOffsetZ 0
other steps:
joint_origin "JointOrigin8" OffsetX 0 OffsetY 0 OffsetZ 0 AngleZ 0
joint_origin "JointOrigin13" OffsetX 0 OffsetY 0 OffsetZ 0 AngleZ 0
joint_origin "JointOrigin14" OffsetX 0 OffsetY 0 OffsetZ 0 AngleZ 0
create_component "CreateComponent1"
create_component "CreateComponent2"
create_component "CreateComponent3"

design "Balise Verte"
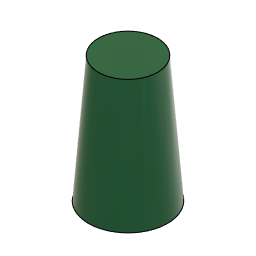
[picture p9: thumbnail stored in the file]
sketch "Sketch1" plane through (0, 0, 0) normal (1, 0, 0) x axis (0, 0, -1)
  line L1 (-36, 0) -> (0, 0)
  line L2 (-27, 115) -> (-36, 0)
  line L3 (0, 115) -> (-27, 115)
  line L4 (0, 0) -> (0, 115)
  line L5 (-25.6128, 113.5) -> (0, 113.5)
  line L6 (-34.4954, 0) -> (-25.6128, 113.5)
  line L7 (0, 0) -> (-34.4954, 0)
  point P1 (0, 0)
  point P2 (0, 0)
  point P6 (0, 0)
  point P7 (0, 113.5)
  point P10 (0, 0)
  point P4 (-27, 115)
  point P5 (0, 115)
  point P3 (-36, 0)
  coincident P1 P2
  horizontal L1
  parallel L1 L3
  coincident P1 P6
  perpendicular L1 L4
  coincident L4 P7
  perpendicular L4 L5
  coincident L4 P10
  perpendicular L4 L7
  collinear L1 L7
  parallel L2 L6
  dimension "d1" distance P4 P5 = 27 (= "( 54 / 2 ) * 1 mm")
  dimension "d2" distance L1 L3 = 115
  dimension "d3" distance P2 P3 = 36 (= "( 72 / 2 ) * 1 mm")
  dimension "d5" distance L3 L5 = 1.5
  dimension "d6" distance L2 L6 = 1.5
revolve "Revolve1" sketch "Sketch1" AlongAngle 360

design "Edge Beacon Left" references "EdgeBeacons_SmallBorder", "EdgeBeacons_LargeBorder", "EdgeBeacons_Base"
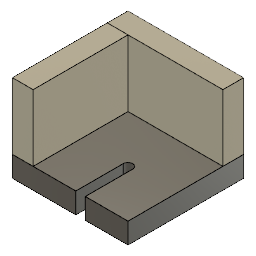
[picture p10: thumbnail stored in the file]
component_insert "Component Insert1"
ground "Ground1"
component_insert "Component Insert2"
component_insert "Component Insert3"
joint "Assemble1" OffsetX 0 OffsetY 0 OffsetZ 0 AngleZ 0 OffsetX 0 OffsetY 0 OffsetZ 0 AngleZ 0 alignAngle 0 alignOffsetX 0 alignOffsetY 0 alignOffsetZ 0
joint "Assemble2" OffsetX 0 OffsetY 0 OffsetZ 0 AngleZ 0 OffsetX 0 OffsetY 0 OffsetZ 0 AngleZ 0 alignAngle 0 alignOffsetX 0 alignOffsetY 0 alignOffsetZ 0

design "Ground"
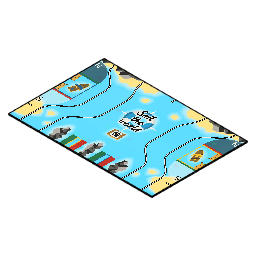
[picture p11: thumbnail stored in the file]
sketch "Sketch1" plane through (0, 0, 0) normal (0, 1, 0) x axis (1, 0, 0)
  line L1 (3000, 0) -> (0, 0)
  line L2 (3000, -2000) -> (3000, 0)
  line L3 (0, -2000) -> (3000, -2000)
  line L4 (0, 0) -> (0, -2000)
  point P1 (0, 0)
  point P2 (0, 0)
  point P5 (0, -2000)
  point P3 (3000, 0)
  horizontal L1
  vertical L2
  horizontal L3
  vertical L4
  coincident P1 P2
  dimension "d1" distance P2 P5 = 2000
  dimension "d2" distance P1 P3 = 3000
  dimension "d5" AlongDistance = 0.1
  dimension "d6" TaperAngle = 0
  dimension "d7" distance = 300
  dimension "d8" distance = 450
  dimension "d12" uSpaceDistance = -300
  dimension "d13" vSpaceDistance = 0
  dimension "d15" distance = 1050
  dimension "d16" distance = 1000
  dimension "d17" diameter = 300
  dimension "d18" AlongDistance = 0.5
  dimension "d19" TaperAngle = 0
  dimension "d21" diameter = 2
  dimension "d22" AlongDistance = 0.1
  dimension "d23" TaperAngle = 0
  dimension "d24" distance = 300
  dimension "d25" distance = 50
  dimension "d30" AlongDistance = 0.2
  dimension "d31" TaperAngle = 0
  dimension "d32" diameter = 299.8
extrude "Extrude1" new body sketch "Sketch1" along normal blind 22
decal "Decal2"
decal "Decal3"
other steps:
decal "Decal1"

design "ROUE_V3"
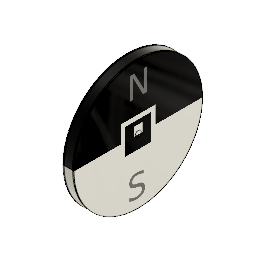
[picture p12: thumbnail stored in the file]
